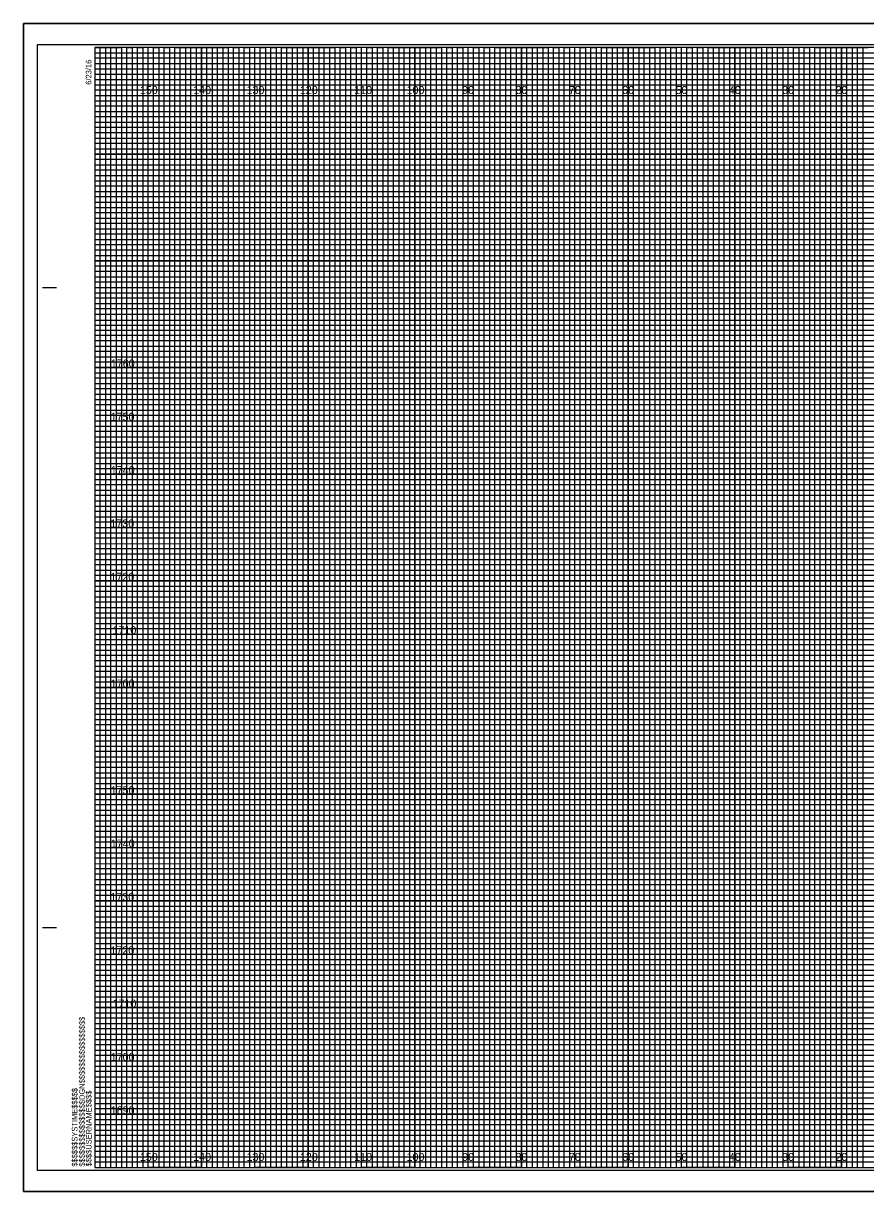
# Model space of a CAD drawing. Extents: x -419 to 4739, y -630 to 13534.
# Drawn here: x -13.4 to 144.5, y 875.5 to 1094.5 of the extents above; entities that cross this region are included whole.
import ezdxf

# ---------------------------------------------------------------- set-up
doc = ezdxf.new("R2010")
doc.units = 0
for name, color, linetype in [('Old_Level_62', 7, 'Continuous'), ('Pattern 1', 7, 'Continuous'), ('Pattern 18', 7, 'Continuous'), ('Pattern 4', 7, 'Continuous'), ('Pattern 5', 7, 'Continuous'), ('Prop Dimension', 7, 'Continuous'), ('Prop Horizontal Alignment', 7, 'Continuous'), ('Raster_Level_0', 7, 'Continuous'), ('Scratch_Level_0', 7, 'Continuous'), ('Scratch_Level_3', 7, 'Continuous'), ('Scratch_Level_5', 7, 'Continuous')]:
    doc.layers.add(name, color=color, linetype=linetype)

msp = doc.modelspace()

# ---------------------------------------------------------------- linework, layer by layer
at = {"layer": 'Old_Level_62'}
for p, q in [((-9.8, 1045), (-7.3, 1045)), ((-9.7, 1045), (-7.2, 1045)), ((-9.8, 925), (-7.3, 925)), ((-9.7, 925), (-7.2, 925)), ((0, 880), (0, 880)), ((0, 880), (0, 880)), ((0, 880), (0, 880)), ((0, 880), (0, 880)), ((0, 880), (0, 880)), ((0, 880), (0, 880)), ((0, 880), (0, 880))]:
    msp.add_line(p, q, dxfattribs=at)
msp.add_lwpolyline([(320, 1090), (0, 1090), (0, 880), (320, 880)], close=True, dxfattribs=at)
at = {"layer": 'Pattern 18'}
for points in [[(-13.4, 875.5), (323.3, 875.5), (323.3, 1094.5), (-13.4, 1094.5)], [(-13.4, 1094.5), (323.3, 1094.5), (323.3, 875.5), (-13.4, 875.5)]]:
    msp.add_lwpolyline(points, close=True, dxfattribs=at)
at = {"layer": 'Pattern 4'}
for p, q in [((0, 1089), (260, 1089)), ((260, 1087.98), (0, 1087.98)), ((0, 1087.98), (0, 1087)), ((0, 1087), (260, 1087)), ((260, 1085.89), (0, 1085.89)), ((0, 1085.89), (0, 1084)), ((0, 1084), (320, 1084))]:
    msp.add_line(p, q, dxfattribs=at)
for points in [[(0, 1083), (270, 1083), (320, 1083), (320, 1082), (0, 1082)], [(0, 1081), (320, 1081), (320, 1079), (0, 1079)], [(0, 1078), (320, 1078), (320, 1077), (0, 1076.98)], [(0, 1076), (320, 1076), (320, 1074), (0, 1074)], [(0, 1073), (320, 1073), (320, 1072), (0, 1072)], [(0, 1071), (320, 1071), (320, 1069), (0, 1069)], [(0, 1068), (320, 1068), (320, 1067), (0, 1067)], [(0, 1066), (320, 1066), (320, 1064), (0, 1064)], [(0, 1063), (320, 1063), (320, 1062), (0, 1062)], [(0, 1061), (320, 1061), (320, 1059), (0, 1059)], [(0, 1058), (320, 1058), (320, 1057), (0, 1057)], [(0, 1056), (320, 1056), (320, 1053.95), (320, 1053), (320, 1052), (0, 1052)], [(0, 1054), (320, 1054), (320, 1053), (0, 1053)], [(0, 1051), (320, 1051), (320, 1049), (0, 1049.03)], [(0, 1049.03), (320, 1049), (320, 1048), (0, 1048)], [(0, 1047), (320, 1047), (320, 1046), (0, 1046)], [(0, 1044), (320, 1044), (320, 1043), (0, 1043)], [(0, 1042), (320, 1042), (320, 1041), (0, 1041)], [(-0.07, 1038.89), (320, 1038.89), (320, 1037.88), (-0.07, 1037.88)], [(0, 1037), (320, 1037), (320, 1036), (0, 1036)], [(0, 1034), (320, 1034), (320, 1033), (0, 1033)], [(0, 1032), (320, 1032), (320, 1031), (0, 1031)], [(0, 1029), (320, 1029), (320, 1028), (0, 1028)], [(0, 1027), (320, 1027), (320, 1026), (0, 1026)], [(0, 1024), (320, 1024), (320, 1023), (0, 1023)], [(0, 1022), (320, 1022), (320, 1021), (0, 1021)], [(0, 1019), (320, 1019), (319.99, 1017.98), (0, 1018)], [(0, 1017), (320, 1017), (320, 1016), (0, 1016)], [(0, 1014), (320, 1014), (320, 1013), (0, 1013)], [(0, 1012), (320, 1012), (320, 1011), (0, 1011)], [(0, 1009), (320, 1009), (320, 1008), (0, 1008)], [(0, 1007), (320, 1007), (320, 1006), (0, 1006)], [(0, 1004), (320, 1004), (320, 1003), (0, 1003)], [(0, 1002), (320, 1002), (320, 1001), (0, 1001)], [(0, 999), (320, 999), (320, 998), (0, 998)], [(0, 996.99), (320.07, 996.91), (320, 996), (0, 996)], [(0, 994), (320, 994), (320, 993), (0, 993)], [(0, 992), (320, 992), (320, 991), (0, 991)], [(0, 989), (320, 989), (320, 988), (0, 988)], [(0, 987), (320, 987), (320, 986), (0, 986)], [(0, 984), (320, 984), (320, 983), (0, 983)], [(0, 982), (320, 982), (320, 981), (0, 981)], [(0, 979), (320, 979), (320, 978), (0, 978)], [(0, 977), (320, 977), (320, 976), (0, 976)], [(0, 974), (320, 974), (320, 973), (0, 973)], [(0, 972), (320, 972), (320, 971), (0, 971)], [(0, 969), (320, 969), (320, 968), (0, 968)], [(0, 967), (320, 967), (320, 966), (0, 966)], [(0, 964), (320, 964), (320, 963), (0, 963)], [(0, 962), (320, 962), (320, 961), (0, 961)], [(0, 959), (320, 959), (319.99, 957.98), (0, 958)], [(0, 957), (320, 957), (320, 956), (0, 956)], [(0, 954), (320, 954), (320, 953), (0, 953)], [(0, 952), (320, 952), (320, 951), (0, 951)], [(0, 949), (320, 949), (320, 948), (0, 948)], [(0, 947), (320, 947), (320, 946), (0, 946)], [(0, 944), (320, 944), (320, 943), (0, 943)], [(0, 942), (320, 942), (320, 941), (0, 941)], [(0, 939), (320, 939), (320, 938), (0, 938)], [(0, 936.99), (320.07, 936.91), (320, 936), (0, 936)], [(0, 934), (320, 934), (320, 933), (0, 933)], [(0, 932), (320, 932), (320, 931), (0, 931)], [(0, 929), (320, 929), (320, 928), (0, 928)], [(0, 927), (320, 927), (320, 926), (0, 926)], [(0, 924), (320, 924), (320, 923), (0, 923)], [(0, 922), (320, 922), (320, 921), (0, 921)], [(0, 919), (320, 919), (320, 918), (0, 918)], [(0, 917), (320, 917), (320, 916), (0, 916)], [(0, 914), (320, 914), (320, 913), (0, 913)], [(0, 912), (320, 912), (320, 911), (0, 911)], [(0, 909), (320, 909), (320, 908), (0, 908)], [(0, 907), (320, 907), (320, 906), (0, 906)], [(0, 904), (320, 904), (320, 903), (0, 903)], [(0, 902), (320, 902), (320, 901), (0, 901)], [(0, 899), (320, 899), (320, 898), (0, 898)], [(0, 897), (320, 897), (320, 896), (0, 896)], [(0, 894), (320, 894), (320, 893), (0, 893)], [(0, 892), (320, 892), (320, 891), (0, 891)], [(0, 889), (320, 889), (320, 888), (0, 888)], [(0, 887), (320, 887), (320, 886), (0, 886)], [(0, 884), (320, 884), (320, 883), (0, 883)], [(0, 882), (320, 882), (320, 881), (0, 881)]]:
    msp.add_lwpolyline(points, dxfattribs=at)
at = {"layer": 'Pattern 5'}
for p, q in [((323.3, 1094.5), (-13.4, 1094.5)), ((-13.4, 1094.5), (-13.4, 875.5)), ((-13.4, 875.5), (323.3, 875.5))]:
    msp.add_line(p, q, dxfattribs=at)
at = {"layer": 'Prop Dimension'}
for points in [[(0, 880), (1, 880), (1, 1090), (2, 1090), (2, 880)], [(2, 880), (3, 880), (3, 1090), (4, 1090), (4, 880)], [(5, 880), (6, 880), (6, 1090), (7, 1090), (7, 880)], [(7, 880), (8, 880), (8, 1090), (9, 1090), (9, 880)], [(10, 880), (11, 880), (11, 1090), (12, 1090), (12, 880)], [(12, 880), (13, 880), (13, 1090), (14, 1090), (14, 880)], [(15, 880), (16, 880), (16, 1090), (17, 1090), (17, 880)], [(17, 880), (18, 880), (18, 1090), (19, 1090), (19, 880)], [(20, 880), (21, 880), (21, 1090), (22, 1090), (22, 880)], [(22, 880), (23, 880), (23, 1090), (24, 1090), (24, 880)], [(25, 880), (26, 880), (26, 1090), (27, 1090), (27, 880)], [(27, 880), (28, 880), (28, 1090), (29, 1090), (29, 880)], [(30, 880), (31, 880), (31, 1090), (32, 1090), (32, 880)], [(32, 880), (33, 880), (33, 1090), (34, 1090), (34, 880)], [(35, 880), (36, 880), (36, 1090), (37, 1090), (37, 880)], [(37, 880), (38, 880), (38, 1090), (39, 1090), (39, 880)], [(40, 880), (41, 880), (41, 1090), (42, 1090), (42, 880)], [(42, 880), (43, 880), (43, 1090), (44, 1090), (44, 880)], [(45, 880), (46, 880), (46, 1090), (47, 1090), (47, 880)], [(47, 880), (48, 880), (48, 1090), (49, 1090), (49, 880)], [(50, 880), (51, 880), (51, 1090), (52, 1090), (52, 880)], [(52, 880), (53, 880), (53, 1090), (54, 1090), (54, 880)], [(55, 880), (56, 880), (56, 1090), (57, 1090), (57, 880)], [(57, 880), (58, 880), (58, 1090), (59, 1090), (59, 880)], [(60, 880), (61, 880), (61, 1090), (62, 1090), (62, 880)], [(62, 880), (63, 880), (63, 1090), (64, 1090), (64, 880)], [(65, 880), (66, 880), (66, 1090), (67, 1090), (67, 880)], [(67, 880), (68, 880), (68, 1090), (69, 1090), (69, 880)], [(70, 880), (71, 880), (71, 1090), (72, 1090), (72, 880)], [(72, 880), (73, 880), (73, 1090), (74, 1090), (74, 880)], [(75, 880), (76, 880), (76, 1090), (77, 1090), (77, 880)], [(77, 880), (78, 880), (78, 1090), (79, 1090), (79, 880)], [(80, 880), (81, 880), (81, 1090), (82, 1090), (82, 880)], [(82, 880), (83, 880), (83, 1090), (84, 1090), (84, 880)], [(85, 880), (86, 880), (86, 1090), (87, 1090), (87, 880)], [(87, 880), (88, 880), (88, 1090), (89, 1090), (89, 880)], [(90, 880), (91, 880), (91, 1090), (92, 1090), (92, 880)], [(92, 880), (93, 880), (93, 1090), (94, 1090), (94, 880)], [(95, 880), (96, 880), (96, 1090), (97, 1090), (97, 880)], [(97, 880), (98, 880), (98, 1090), (99, 1090), (99, 880)], [(100, 880), (101, 880), (101, 1090), (102, 1090), (102, 880)], [(102, 880), (103, 880), (103, 1090), (104, 1090), (104, 880)], [(105, 880), (106, 880), (106, 1090), (107, 1090), (107, 880)], [(107, 880), (108, 880), (108, 1090), (109, 1090), (109, 880)], [(110, 880), (111, 880), (111, 1090), (112, 1090), (112, 880)], [(112, 880), (113, 880), (113, 1090), (114, 1090), (114, 880)], [(115, 880), (116, 880), (116, 1090), (117, 1090), (117, 880)], [(117, 880), (118, 880), (118, 1090), (119, 1090), (119, 880)], [(120, 880), (121, 880), (121, 1090), (122, 1090), (122, 880)], [(122, 880), (123, 880), (123, 1090), (124, 1090), (124, 880)], [(125, 880), (126, 880), (126, 1090), (127, 1090), (127, 880)], [(127, 880), (128, 880), (128, 1090), (129, 1090), (129, 880)], [(130, 880), (131, 880), (131, 1090), (132, 1090), (132, 880)], [(132, 880), (133, 880), (133, 1090), (134, 1090), (134, 880)], [(135, 880), (136, 880), (136, 1090), (137, 1090), (137, 880)], [(137, 880), (138, 880), (138, 1090), (139, 1090), (139, 880)], [(140, 880), (141, 880), (141, 1090), (142, 1090), (142, 880)], [(142, 880), (143, 880), (143, 1090), (144, 1090), (144, 880)]]:
    msp.add_lwpolyline(points, dxfattribs=at)
at = {"layer": 'Prop Horizontal Alignment'}
for points in [[(0, 1090), (5, 1090), (5, 880), (15, 880), (15, 1090), (25, 1090), (25, 880), (35, 880), (35, 1090), (45, 1090), (45, 880), (55, 880), (55, 1090), (65, 1090), (65, 880), (75, 880), (75, 1090), (85, 1090), (85, 880), (95, 880), (95, 1090), (105, 1090), (105, 880), (115, 880), (115, 1090), (125, 1090), (125, 880), (135, 880), (135, 1090), (145, 1090)], [(0, 1085), (275, 1085)], [(0, 1065), (320, 1065), (320, 1075), (0, 1075)], [(0, 1045), (320, 1045), (320, 1055), (0, 1055)], [(0, 1025), (320, 1025), (320, 1035), (0, 1035)], [(0, 1005), (320, 1005), (320, 1015), (0, 1015)], [(0, 985), (320, 985), (320, 995), (0, 995)], [(0, 965), (320, 965), (320, 975), (0, 975)], [(0, 945), (320, 945), (320, 955), (0, 955)], [(0, 925), (320, 925), (320, 935), (0, 935)], [(0, 905), (320, 905), (320, 915), (0, 915)], [(0, 885), (320, 885), (320, 895), (0, 895)]]:
    msp.add_lwpolyline(points, dxfattribs=at)
at = {"layer": 'Scratch_Level_0'}
for p, q in [((10, 880), (10, 1090)), ((20, 880), (20, 1090)), ((30, 880), (30, 1090)), ((40, 880), (40, 1090)), ((50, 880), (50, 1090)), ((60, 880), (60, 1090)), ((70, 880), (70, 1090)), ((80, 880), (80, 1090)), ((90, 880), (90, 1090)), ((100, 880), (100, 1090)), ((110, 880), (110, 1090)), ((120, 880), (120, 1090)), ((130, 880), (130, 1090)), ((140, 880), (140, 1090)), ((0, 1080), (320, 1080)), ((0, 1070), (320, 1070)), ((0, 1060), (320, 1060)), ((0, 1050), (320, 1050)), ((0, 1040), (320, 1040)), ((0, 1030), (320, 1030)), ((0, 1020), (320, 1020)), ((0, 1010), (320, 1010)), ((0, 1000), (320, 1000)), ((0, 990), (320, 990)), ((0, 980), (320, 980)), ((0, 970), (320, 970)), ((0, 960), (320, 960)), ((0, 950), (320, 950)), ((0, 940), (320, 940)), ((0, 930), (320, 930)), ((0, 920), (320, 920)), ((0, 910), (320, 910)), ((0, 900), (320, 900)), ((0, 890), (320, 890))]:
    msp.add_line(p, q, dxfattribs=at)
at = {"layer": 'Scratch_Level_3'}
for p, q in [((10, 1090), (0, 1090)), ((10, 880), (10, 1090)), ((30, 1090), (20, 1090)), ((20, 1090), (20, 880)), ((30, 880), (30, 1090)), ((50, 1090), (40, 1090)), ((40, 1090), (40, 880)), ((50, 880), (50, 1090)), ((70, 1090), (60, 1090)), ((60, 1090), (60, 880)), ((70, 880), (70, 1090)), ((90, 1090), (80, 1090)), ((80, 1090), (80, 880)), ((90, 880), (90, 1090)), ((110, 1090), (100, 1090)), ((100, 1090), (100, 880)), ((110, 880), (110, 1090)), ((130, 1090), (120, 1090)), ((120, 1090), (120, 880)), ((130, 880), (130, 1090)), ((150, 1090), (140, 1090)), ((140, 1090), (140, 880)), ((20, 880), (10, 880)), ((40, 880), (30, 880)), ((60, 880), (50, 880)), ((80, 880), (70, 880)), ((100, 880), (90, 880)), ((120, 880), (110, 880)), ((140, 880), (130, 880))]:
    msp.add_line(p, q, dxfattribs=at)
for points in [[(0, 1080), (320, 1080), (320, 1070), (0, 1070)], [(0, 1060), (320, 1060), (320, 1050), (0, 1050)], [(0, 1040), (320, 1040), (320, 1030), (0, 1030)], [(0, 1020), (320, 1020), (320, 1010), (0, 1010)], [(0, 1000), (320, 1000), (320, 990), (0, 990)], [(0, 980), (320, 980), (320, 970), (0, 970)], [(0, 960), (320, 960), (320, 950), (0, 950)], [(0, 940), (320, 940), (320, 930), (0, 930)], [(0, 920), (320, 920), (320, 910), (0, 910)], [(0, 900), (320, 900), (320, 890), (0, 890)]]:
    msp.add_lwpolyline(points, dxfattribs=at)
at = {"layer": 'Scratch_Level_5'}
msp.add_lwpolyline([(-10.8, 879.5), (322.4, 879.5), (322.4, 1090.5), (-10.8, 1090.5)], close=True, dxfattribs=at)

# ---------------------------------------------------------------- texts
at = {"layer": 'Old_Level_62'}
for s, p in [('6/23/16', (-0.65, 1083)), ('$$$$$$$$$$$$$$$$DGN$$$$$$$$$$$$$$$$', (-1.88, 880.18)), ('$$$$$$SYSTIME$$$$$', (-3.26, 880.18)), ('$$$$USERNAME$$$$', (-0.62, 880.23))]:
    msp.add_text(s, height=1.05, rotation=90, dxfattribs=at).set_placement(p)
at = {"layer": 'Pattern 1'}
for s, p in [('1760', (3, 1030)), ('1750', (2.96, 1020)), ('1740', (3, 1010)), ('1730', (2.92, 1000)), ('1720', (2.93, 990)), ('1710', (3.31, 980)), ('1700', (2.98, 970)), ('1750', (2.96, 950)), ('1740', (3, 940)), ('1730', (2.92, 930)), ('1720', (2.93, 920)), ('1710', (3.31, 910)), ('1700', (2.98, 900)), ('1690', (2.97, 890))]:
    msp.add_text(s, height=1.5, dxfattribs=at).set_placement(p)
at = {"layer": 'Raster_Level_0'}
for s, p in [('150', (8.44, 1081.25)), ('140', (18.44, 1081.25)), ('130', (28.44, 1081.25)), ('120', (38.44, 1081.25)), ('110', (48.62, 1081.25)), ('100', (58.44, 1081.25)), ('90', (68.86, 1081.25)), ('80', (78.86, 1081.25)), ('70', (88.86, 1081.25)), ('60', (98.86, 1081.25)), ('50', (108.86, 1081.25)), ('40', (118.86, 1081.25)), ('30', (128.86, 1081.25)), ('20', (138.86, 1081.25)), ('150', (8.44, 881.25)), ('140', (18.44, 881.25)), ('130', (28.44, 881.25)), ('120', (38.44, 881.25)), ('110', (48.62, 881.25)), ('100', (58.44, 881.25)), ('90', (68.86, 881.25)), ('80', (78.86, 881.25)), ('70', (88.86, 881.25)), ('60', (98.86, 881.25)), ('50', (108.86, 881.25)), ('40', (118.86, 881.25)), ('30', (128.86, 881.25)), ('20', (138.86, 881.25))]:
    msp.add_text(s, height=1.5, dxfattribs=at).set_placement(p)

doc.saveas('drawing.dxf')
